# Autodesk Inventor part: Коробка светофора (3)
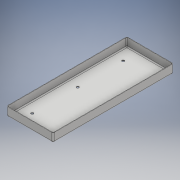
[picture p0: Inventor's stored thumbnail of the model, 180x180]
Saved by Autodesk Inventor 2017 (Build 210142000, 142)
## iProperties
Part Number: Коробка светофора (3)
Material: Типовые
Document SubType Name: Modeling
Designer: Система Знаний
Density: 1 g/cm^3
Appearance: По умолчанию
Author: Система Знаний
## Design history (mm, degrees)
sketch "Эскиз1"
  geometry: L1 (0, 0)-(190, 0); L2 (190, 0)-(190, -490); L3 (190, -490)-(0, -490); L4 (0, -490)-(0, 0)
  constraints: 8 end point, 2 parallel, 1 horizontal, 1 perpendicular
  dimensions: "d0" = 190 distance of L2.end L3.end; "d1" = 490 distance of L1.end L2.end
extrude "Выдавливание1" new body sketch "Эскиз1" distance "d2" = 35; taper "d3" = 0 deg
feature "Оболочка1" dims "d4" = 2
sketch "Эскиз3"
  geometry: L1 (-190, 0)-(-190, -490) reference; L2 (0, 0)-(-190, 0); L3 (-190, 0)-(-190, -490); L4 (-190, -490)-(0, -490); L5 (0, -490)-(0, 0)
  constraints: 8 end point, 2 parallel, 1 horizontal, 1 perpendicular
extrude "Выдавливание2" join sketch "Эскиз3" distance "d10" = 1; taper "d11" = 0 deg
fillet "Сопряжение4" dims "d13" = 6
fillet "Сопряжение5" dims "d14" = 4
sketch "Эскиз4"
  geometry: C1 r 5 at (-45, -245); C2 r 5 at (-45, -429.905); C3 r 5 at (-45, -60.095); 5 further points
  constraints: 4 coincident, 3 centre point
  dimensions: "d19" = 10 diameter of C1; "d21" = 10 diameter of C2; "d22" = 10 diameter of C3
hole "Отверстие1" sketch "Эскиз4" at (-45, -60.095), (-45, -245), (-45, -429.905), (-45, -60.095) diameter "d23" = 10; stored, may be unused: countersink angle "d27" = 90 deg, drill point angle "d29" = 118 deg; dims "d24" = 6, "d25" = 11, "d26" = 1, "d28" = 10 (= d19)
node "Твердое тело1"
